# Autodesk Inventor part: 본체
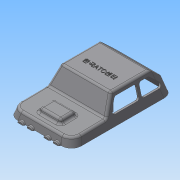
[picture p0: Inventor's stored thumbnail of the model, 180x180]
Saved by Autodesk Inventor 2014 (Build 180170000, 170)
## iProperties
Created: 2015-05
Part Number: 본체
Material: Generic
Document SubType Name: Modeling
Designer: Administrator
Density: 1 g/cm^3
Appearance: Default
Author: Administrator
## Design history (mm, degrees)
sketch "스케치5"
  geometry: L1 (0, 0)-(-122, 0); L2 (-122, 0)-(-119.249, 10.269); L3 (-119.249, 10.269)-(-77.932, 11); L4 (-77.932, 11)-(-67.133, 31); L5 (-67.133, 31)-(-21.792, 31); L6 (-21.792, 31)-(-3.909, 14.587); L7 (-3.909, 14.587)-(0, 0); L8 (0, 0)-(0, 11); L9 (-5.051, 15.636)-(0, 11)
  constraints: 18 end point, 2 horizontal, 1 collinear, 1 perpendicular, 1 point on line
  dimensions: "d44" = 122 distance of L1.start L1.end; "d45" = 105 deg angle of L2 L1; "d46" = 105 deg angle of L7 L1; "d47" = 31 distance between parallel lines of L1 L5; "d48" = 20 vertical distance of L3.end L4.end; "d49" = 20 vertical distance of L8.end L5.end
extrude "돌출5" new body sketch "스케치5" stored distance "d50" = 76; taper "d51" = 0 deg
node "작업 평면4"
sketch "스케치6"
  geometry: L1 (0, -114.412)-(0, -86.69); L2 (0, -86.69)-(-15.739, -92.736); L3 (-11, -77.932)-(-10.269, -119.249) reference; L4 (-15.739, -92.736)-(-15.449, -109.097); L5 (-15.449, -109.097)-(0, -114.412); L6 (-10.269, -119.249)-(0, -122) reference; L7 (-10.269, -119.249)-(-10.223, -121.828); L8 (0, -122)-(0, 0) reference; 2 further points
  constraints: 10 end point, 5 point on line, 1 parallel, 1 vertical
  dimensions: "d52" = 70 deg angle of L5 L3; "d53" = 70 deg angle of L2 L3; "d54" = 11 vertical distance of L7.end point (-10.418, -110.828); "d55" = 5 distance between parallel lines of L4 L3; "d56" = 20 vertical distance of point (-10.772, -90.828) point (-10.418, -110.828)
extrude "돌출6" join sketch "스케치6" stored distance "d57" = 26; taper "d58" = 0 deg
sketch "스케치9"
  geometry: L1 (38, 31)-(38, 0); L2 (-38, 0)-(-38, 31); L3 (-38, 0)-(-29.694, 31); L4 (29.694, 31)-(38, 0); L5 (-38, 31)-(-29.694, 31); L6 (29.694, 31)-(38, 31); L7 (38, 0)-(-38, 0) reference; L8 (38, 31)-(38, 14.587) reference; 5 further points
  constraints: 12 end point, 4 midpoint, 2 horizontal, 2 horizontal alignment, 2 perpendicular, 2 point on line, 1 parallel
  dimensions: "d74" = 15 deg angle of L1 L4; "d75" = 15 deg angle of L2 L3
extrude "돌출7" cut sketch "스케치9" stored distance "d76" = 26; taper "d77" = 0 deg
sketch "스케치10"
  geometry: L1 (-26, -64.151)-(-11, -72.249); L2 (-11, -72.249)-(-11, -38.249); L3 (-11, -38.249)-(-26, -38.249); L4 (-26, -38.249)-(-26, -64.151); L5 (-26, -35.395)-(-11, -35.395); L6 (-11, -35.395)-(-11, -7.395); L7 (-11, -7.395)-(-26, -23.739); L8 (-26, -23.739)-(-26, -35.395); L9 (-11, -77.932)-(-31, -67.133) reference; L10 (-31, -67.133)-(-31, -21.792) reference; L11 (-31, -21.792)-(-14.587, -3.909) reference; 1 further point
  constraints: 16 end point, 4 perpendicular, 3 parallel, 1 vertical
  dimensions: "d79" = 34 distance of L1.end L2.end; "d80" = 5 distance between parallel lines of L9 L1; "d81" = 5 distance between parallel lines of L11 L7; "d82" = 5 distance between parallel lines of L10 L8; "d83" = 5 distance between parallel lines of L10 L4; "d84" = 15 distance between parallel lines of L4 L2; "d86" = 28 distance of L5.end L6.end; "d130" = 15 horizontal distance of L6.end L7.end
fillet "모깎기2" dims "d87" = 12
feature "쉘3" dims "d88" = 2
extrude "돌출8" cut sketch "스케치10" stored distance "d89" = 26; taper "d90" = 0 deg
fillet "모깎기3" dims "d91" = 3
fillet "모깎기4" dims "d92" = 3
fillet "모깎기5" dims "d93" = 3
fillet "모깎기6" dims "d94" = 3
fillet "모깎기7" dims "d95" = 3
sketch "스케치11"
  geometry: L1 (0.139, -2.071)-(52.679, -2.071) reference; L2 (62.338, -11.73)-(62.338, -110.27) reference; L3 (52.679, -119.929)-(0.139, -119.929) reference; L4 (-9.521, -110.27)-(-9.521, -11.73) reference; L5 (52.818, 0)-(0, 0) reference; L6 (-11.591, -110.409)-(-11.591, -11.591) reference; L7 (0, -122)-(52.818, -122) reference; L8 (64.409, -11.591)-(64.409, -110.409) reference; 9 further points; 8 other entities
  constraints: 8 other
sketch "스케치12"
  geometry: L1 (0, 0)-(54.783, 0) reference; L2 (0.983, 22.96)-(53.8, 22.96) reference; 3 further points
  constraints: 1 midpoint, 1 vertical alignment, 1 other
  dimensions: "d96" = 50 distance of point (27.392, 22.96) point (27.392, -27.04)
feature "엠보싱1" sketch "스케치12" dims "d55" = 5, "d97" = 0.5, "d98" = 0
node "작업 평면5"
sketch "스케치13"
  geometry: L1 (-32.409, 0)-(-20.409, 0); L2 (-51.409, 0)-(-43.409, 0); L3 (-40.409, 0)-(-32.409, 0); L4 (-20.409, 0)-(-12.409, 0); L5 (-9.409, 0)-(-1.409, 0); A1 r 4 centre (-47.409, 0) between (-43.409, 0) and (-51.409, 0); A2 r 4 centre (-36.409, 0) between (-32.409, 0) and (-40.409, 0); A3 r 4 centre (-16.409, 0) between (-12.409, 0) and (-20.409, 0); A4 r 4 centre (-5.409, 0) between (-1.409, 0) and (-9.409, 0); 3 further points
  constraints: 10 end point, 10 point on circle, 4 centre point, 1 coincident, 1 collinear, 1 midpoint
  dimensions: "d100" = 4 radius of A1; "d101" = 4 radius of A2; "d102" = 4 radius of A3; "d103" = 4 radius of A4; "d104" = 11 distance of A2.centre A1.centre; "d105" = 11 distance of A4.centre A3.centre; "d106" = 20 distance of A2.centre A3.centre; "d107" = 8 distance of L5.start L5.end; "d108" = 8 distance of L1.end L4.end
extrude "돌출9" join sketch "스케치13" stored distance "d109" = 4; taper "d110" = 0 deg
chamfer "모따기1" distance "d111" = 1; stored, may be unused: second distance "d112" = 2, angle "d113" = 45 deg
extrude "돌출10" cut sketch "스케치11" distance "d122" = 1; taper "d123" = 0 deg
sketch "스케치16"
  geometry: L1 (7, 2)-(-1, 2) reference; L2 (-1, 1)-(-1, 2) reference; L3 (0, 0)-(-1, 1) reference; L4 (6, 0)-(0, 0) reference; L5 (7, 1)-(6, 0) reference; L6 (7, 2)-(7, 1) reference; L7 (7, 2)-(-1, 2) reference; L8 (-1, 1)-(-1, 2) reference; L9 (0, 0)-(-1, 1) reference; L10 (6, 0)-(0, 0) reference; L11 (7, 1)-(6, 0) reference; L12 (7, 2)-(7, 1) reference; L13 (18, 2)-(10, 2) reference; L14 (10, 1)-(10, 2) reference; L15 (11, 0)-(10, 1) reference; L16 (17, 0)-(11, 0) reference; L17 (18, 1)-(17, 0) reference; L18 (18, 2)-(18, 1) reference; L19 (38, 2)-(30, 2) reference; L20 (30, 1)-(30, 2) reference; L21 (31, 0)-(30, 1) reference; L22 (37, 0)-(31, 0) reference; L23 (38, 1)-(37, 0) reference; L24 (38, 2)-(38, 1) reference; L25 (49, 2)-(41, 2) reference; L26 (41, 1)-(41, 2) reference; L27 (42, 0)-(41, 1) reference; L28 (48, 0)-(42, 0) reference; L29 (49, 1)-(48, 0) reference; L30 (49, 2)-(49, 1) reference; 1 further point
extrude "돌출11" cut sketch "스케치16" distance "d124" = 1; taper "d125" = 0 deg
sketch "스케치21"
  geometry: C1 r 2 at (26.409, -100.945); C2 r 2 at (26.409, -22.585); C3 r 2 at (5.409, -61); C4 r 2 at (44.58, -61); 1 further point
  constraints: 4 centre point
  dimensions: "d138" = 4 diameter of C1; "d139" = 4 diameter of C2; "d140" = 4 diameter of C3; "d141" = 4 diameter of C4
extrude "돌출13" join sketch "스케치21" stored distance "d142" = 61.5; taper "d143" = 0 deg
sketch "스케치22"
  geometry: L1 (-0.5, -5)-(0.5, -5); L2 (0.5, -5)-(0.5, 5); L3 (0.5, 5)-(-0.5, 5); L4 (-0.5, 5)-(-0.5, -5); L5 (-0.5, -5)-(0.5, 5); L6 (0.5, -5)-(-0.5, 5); L7 (-20.5, 34.945)-(-20.5, 44.945); L8 (-21.5, 44.945)-(-21.5, 34.945); L9 (-20.5, 44.945)-(-21.5, 44.945); L10 (-21.5, 34.945)-(-20.5, 34.945); L11 (0.5, 73.36)-(0.5, 83.36); L12 (-0.5, 83.36)-(-0.5, 73.36); L13 (0.5, 83.36)-(-0.5, 83.36); L14 (-0.5, 73.36)-(0.5, 73.36); L15 (18.672, 34.945)-(18.672, 44.945); L16 (17.672, 44.945)-(17.672, 34.945); L17 (18.672, 44.945)-(17.672, 44.945); L18 (17.672, 34.945)-(18.672, 34.945); C1 r 2 at (0, 0) reference; C2 r 2 at (18.172, 39.945) reference; C3 r 2 at (-21, 39.945) reference; C4 r 2 at (0, 78.36) reference; 1 further point
  constraints: 36 end point, 8 parallel, 4 horizontal, 4 perpendicular, 2 midpoint
  dimensions: "d144" = 10 distance of L3.end L1.start; "d145" = 1 distance of L2.end L3.end; "d146" = 10 distance of L8.start L8.end; "d147" = 1 distance of L7.end L8.start; "d148" = 10 distance of L12.start L12.end; "d149" = 1 distance of L11.end L12.start; "d150" = 10 distance of L16.start L16.end; "d151" = 1 distance of L15.end L16.start
extrude "돌출14" join sketch "스케치22" stored distance "d152" = 0; taper "d153" = 0 deg
sketch "스케치23"
  geometry: L1 (26.909, -99.009)-(26.909, -95.945) reference; L2 (26.909, -95.945)-(25.909, -95.945) reference; L3 (25.909, -95.945)-(25.909, -99.009) reference; L4 (25.909, -102.882)-(25.909, -105.945) reference; L5 (25.909, -105.945)-(26.909, -105.945) reference; L6 (26.909, -105.945)-(26.909, -102.882) reference; L7 (45.08, -56)-(45.08, -59.064) reference; L8 (44.08, -56)-(45.08, -56) reference; L9 (44.08, -59.064)-(44.08, -56) reference; L10 (44.08, -66)-(44.08, -62.936) reference; L11 (45.08, -66)-(44.08, -66) reference; L12 (45.08, -62.936)-(45.08, -66) reference; L13 (5.909, -56)-(5.909, -59.064) reference; L14 (4.909, -56)-(5.909, -56) reference; L15 (4.909, -59.064)-(4.909, -56) reference; L16 (4.909, -66)-(4.909, -62.936) reference; L17 (5.909, -66)-(4.909, -66) reference; L18 (5.909, -62.936)-(5.909, -66) reference; A1 r 2 centre (26.409, -22.585) between (25.909, -20.649) and (25.909, -24.522) reference; A2 r 2 centre (26.409, -100.945) between (26.909, -102.882) and (26.909, -99.009) reference; A3 r 2 centre (26.409, -100.945) between (25.909, -99.009) and (25.909, -102.882) reference; A4 r 2 centre (44.58, -61) between (45.08, -62.936) and (45.08, -59.064) reference; A5 r 2 centre (44.58, -61) between (44.08, -59.064) and (44.08, -62.936) reference; A6 r 2 centre (5.409, -61) between (5.909, -62.936) and (5.909, -59.064) reference; A7 r 2 centre (5.409, -61) between (4.909, -59.064) and (4.909, -62.936) reference; 5 further points
  constraints: 4 coincident
hole "구멍1" sketch "스케치23" at (5.409, -61), (26.409, -100.945), (44.58, -61), (26.409, -22.585) diameter "d154" = 3.242; stored, may be unused: countersink angle "d158" = 90 deg, drill point angle "d160" = 118 deg; dims "d155" = 9, "d156" = 4, "d157" = 2, "d159" = 11
sketch "스케치24"
  geometry: C1 r 2 at (5.409, -61); C2 r 3 at (5.409, -61); C3 r 3 at (44.552, -61); C4 r 2 at (44.552, -61); C5 r 3 at (26.409, -22.596); C6 r 2 at (26.409, -22.596); C7 r 3 at (26.409, -100.941); C8 r 2 at (26.409, -100.941); A1 r 2 centre (5.409, -61) between (5.909, -62.936) and (5.909, -59.064) reference; A2 r 2 centre (5.409, -61) between (4.909, -59.064) and (4.909, -62.936) reference; 1 further point
  constraints: 8 centre point, 5 coincident, 1 concentric
  dimensions: "d161" = 6 diameter of C2; "d162" = 6 diameter of C3; "d163" = 6 diameter of C5; "d164" = 6 diameter of C7
extrude "돌출15" join sketch "스케치24" stored distance "d165" = 1; taper "d166" = 0 deg
node "솔리드2"
node "투영된 루프3"
node "투영된 루프4"
node "투영된 루프5"
node "투영된 루프6"
node "투영된 루프8"
node "투영된 루프9"
node "투영된 루프10"
other parameters: "d18" = 5, "d61" = 5
